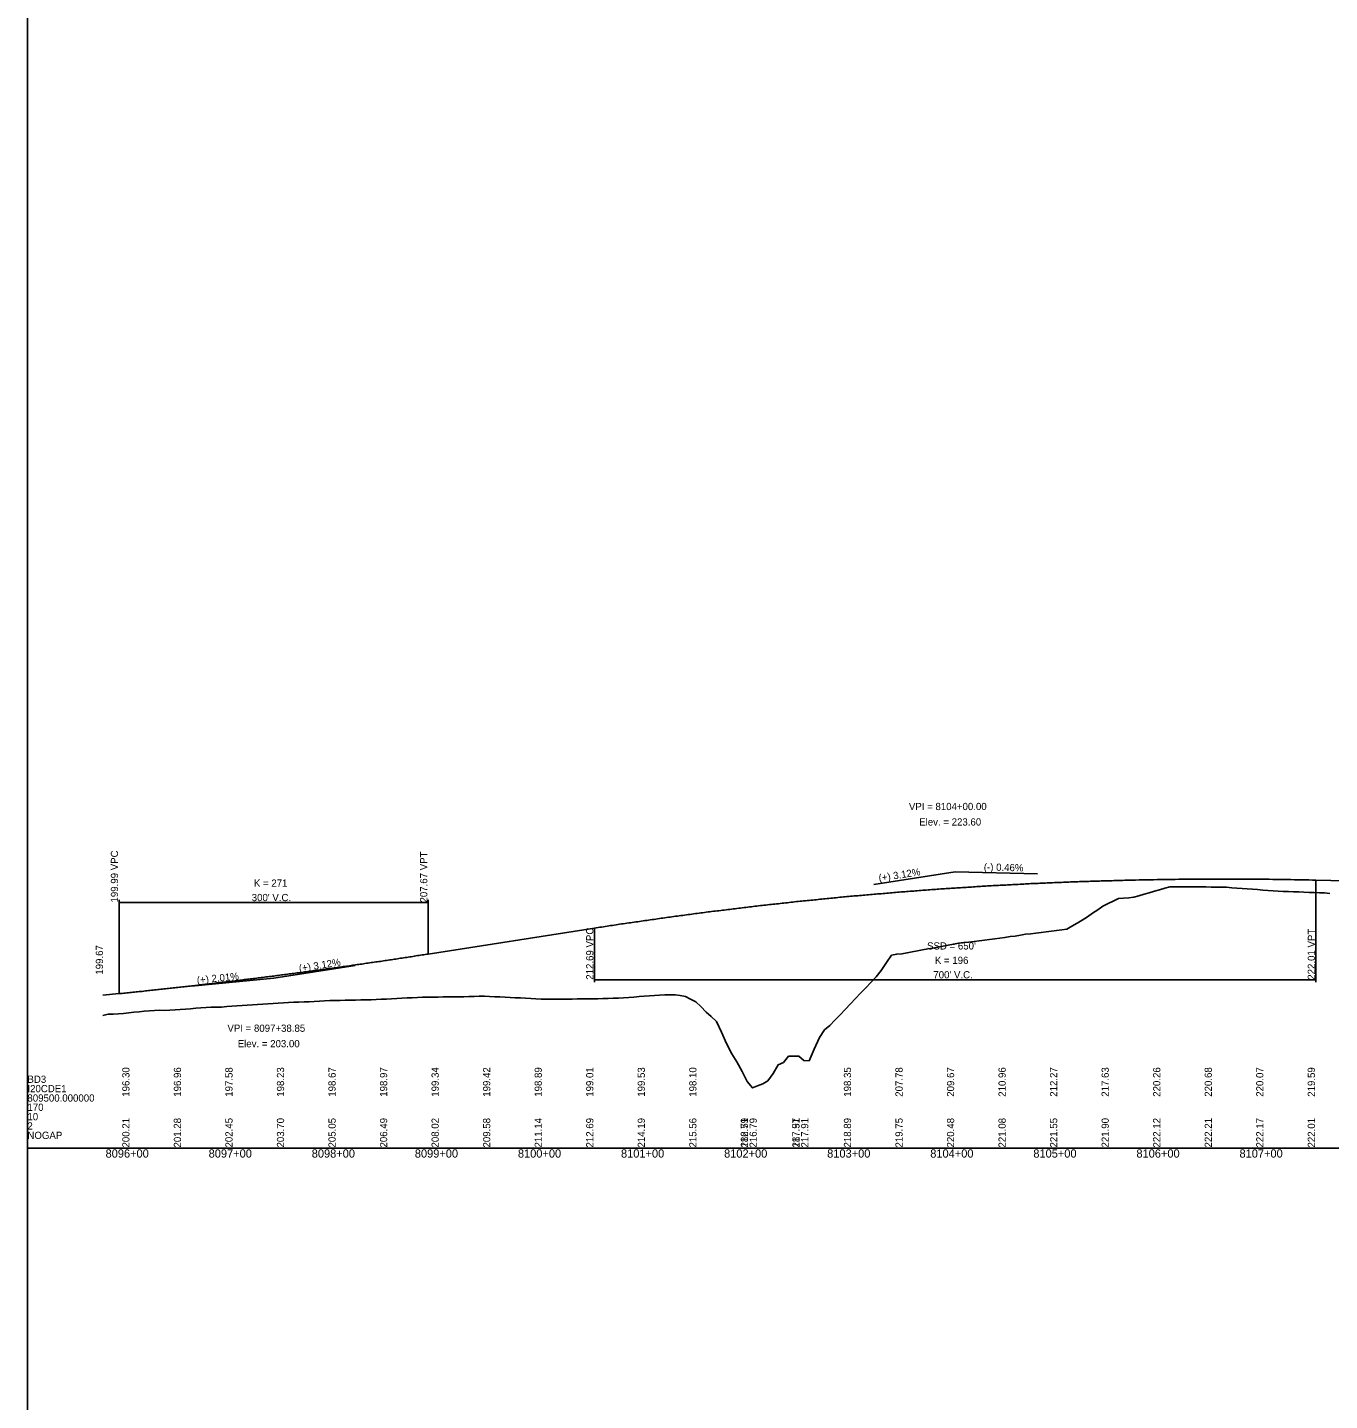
# Model space of a CAD drawing. Extents: x 1838386 to 1955906, y 719739 to 834437.
# Drawn here: x 1895682 to 1896945, y 773245 to 774576 of the extents above; entities that cross this region are included whole.
import ezdxf

# ---------------------------------------------------------------- set-up
doc = ezdxf.new("R2010")
doc.units = 0
for name, color, linetype in [('RD_DDB_GradeTX', 7, 'Continuous'), ('RD_DDB_Profile_EX', 7, 'Continuous'), ('RD_DDB_Profile_Lbl', 7, 'Continuous'), ('RD_DDB_Profile_PR', 7, 'Continuous'), ('RD_DDB_StaTX', 7, 'Continuous'), ('RD_DDB_StripGrade', 7, 'Continuous'), ('RD_DDB_VCLbl', 7, 'Continuous'), ('RD_GPK_Profile_Cell', 7, 'Continuous')]:
    doc.layers.add(name, color=color, linetype=linetype)

msp = doc.modelspace()

# ---------------------------------------------------------------- linework, layer by layer
at = {"layer": 'RD_DDB_GradeTX'}
for p, q in [((1896502.6, 773744.8), (1896581.6, 773757.1)), ((1896661.6, 773755.3), (1896581.6, 773757.1)), ((1895999.5, 773666.5), (1895920.5, 773654.1)), ((1895840.9, 773646.2), (1895920.5, 773654.1))]:
    msp.add_line(p, q, dxfattribs=at)
at = {"layer": 'RD_DDB_Profile_EX'}
for points in [[(1896754.9, 773732.6), (1896759.9, 773734), (1896764.9, 773735.5), (1896769.9, 773736.9), (1896774.9, 773738.4), (1896779.9, 773739.9), (1896784.9, 773741.4), (1896789.9, 773742.6), (1896794.9, 773742.6), (1896799.9, 773742.6), (1896804.9, 773742.6), (1896809.9, 773742.6), (1896814.9, 773742.6), (1896819.9, 773742.6), (1896824.9, 773742.6), (1896829.9, 773742.5), (1896834.9, 773742.5), (1896839.9, 773742.5), (1896844.9, 773742.2), (1896849.9, 773741.8), (1896854.9, 773741.5), (1896859.9, 773741.1), (1896864.9, 773740.7), (1896869.9, 773740.3), (1896874.9, 773740), (1896879.9, 773739.6), (1896884.9, 773739.2), (1896889.9, 773738.9), (1896894.9, 773738.5), (1896899.9, 773738.3), (1896904.9, 773738.1), (1896909.9, 773737.9), (1896914.9, 773737.7), (1896919.9, 773737.5), (1896924.9, 773737.3), (1896929.9, 773737.1), (1896934.9, 773737), (1896939.9, 773736.8), (1896944.9, 773736.3)], [(1896254.9, 773634.8), (1896259.9, 773635), (1896264.9, 773635.4), (1896269.9, 773635.8), (1896274.9, 773636.3), (1896279.9, 773636.7), (1896284.9, 773637), (1896289.9, 773637.2), (1896294.9, 773637.5), (1896299.9, 773637.8), (1896304.9, 773638.1), (1896309.9, 773638.1), (1896314.9, 773637.3), (1896319.9, 773636.3), (1896324.9, 773633.7), (1896329.9, 773631.3), (1896334.9, 773626.6), (1896339.9, 773621), (1896344.9, 773617), (1896349.9, 773612.1), (1896354.9, 773601.9), (1896359.9, 773590.9), (1896364.9, 773580.6), (1896369.9, 773573.1), (1896374.9, 773563.5), (1896379.9, 773553.9), (1896384.9, 773547.7), (1896389.9, 773549.7), (1896394.9, 773551.6), (1896399.9, 773554.6), (1896404.9, 773561.5), (1896409.9, 773570.2), (1896414.9, 773572.3), (1896419.9, 773578.6), (1896424.9, 773578.5), (1896429.9, 773578.4), (1896434.9, 773574.4), (1896439.9, 773573.8), (1896444.9, 773585.2), (1896449.9, 773596.6), (1896454.9, 773603.9), (1896459.9, 773608.2), (1896464.9, 773613.4), (1896469.9, 773618.6), (1896474.9, 773623.8), (1896479.9, 773629.1), (1896484.9, 773634.3), (1896489.9, 773639.5), (1896494.9, 773644.8), (1896499.9, 773650), (1896504.9, 773655.3), (1896509.9, 773661.6), (1896514.9, 773669.2), (1896519.9, 773676.3), (1896524.9, 773677.4), (1896529.9, 773677.7), (1896534.9, 773678.7), (1896539.9, 773679.6), (1896544.9, 773680.5), (1896549.9, 773681.5), (1896554.9, 773682.4), (1896559.9, 773683.3), (1896564.9, 773684.3), (1896569.9, 773685.2), (1896574.9, 773686.2), (1896579.9, 773687.2), (1896584.9, 773688.1), (1896589.9, 773688.6), (1896594.9, 773689.1), (1896599.9, 773689.7), (1896604.9, 773690.4), (1896609.9, 773691), (1896614.9, 773691.7), (1896619.9, 773692.4), (1896624.9, 773693), (1896629.9, 773693.7), (1896634.9, 773694.4), (1896639.9, 773695), (1896644.9, 773695.7), (1896649.9, 773696.8), (1896654.9, 773697.2), (1896659.9, 773697.8), (1896664.9, 773698.4), (1896669.9, 773699), (1896674.9, 773699.6), (1896679.9, 773700.3), (1896684.9, 773700.9), (1896689.9, 773701.7), (1896694.9, 773704.6), (1896699.9, 773707.5), (1896704.9, 773710.4), (1896709.9, 773713.7), (1896714.9, 773717), (1896719.9, 773720.4), (1896724.9, 773723.8), (1896729.9, 773726.4), (1896734.9, 773728.9), (1896739.9, 773731.4), (1896744.9, 773731.6), (1896749.9, 773732.1), (1896754.9, 773732.6)], [(1895754.9, 773617.9), (1895759.9, 773619.1), (1895764.9, 773619.1), (1895769.9, 773619.4), (1895774.9, 773619.9), (1895779.9, 773620.5), (1895784.9, 773621), (1895789.9, 773621.5), (1895794.9, 773622), (1895799.9, 773622.5), (1895804.9, 773622.9), (1895809.9, 773623), (1895814.9, 773622.6), (1895819.9, 773623), (1895824.9, 773623.4), (1895829.9, 773623.8), (1895834.9, 773624.2), (1895839.9, 773624.5), (1895844.9, 773624.9), (1895849.9, 773625.3), (1895854.9, 773625.6), (1895859.9, 773625.9), (1895864.9, 773625.9), (1895869.9, 773626.1), (1895874.9, 773626.5), (1895879.9, 773626.9), (1895884.9, 773627.3), (1895889.9, 773627.6), (1895894.9, 773628), (1895899.9, 773628.4), (1895904.9, 773628.7), (1895909.9, 773629), (1895914.9, 773629.3), (1895919.9, 773629.6), (1895924.9, 773629.9), (1895929.9, 773630.2), (1895934.9, 773630.4), (1895939.9, 773630.7), (1895944.9, 773630.9), (1895949.9, 773631.1), (1895954.9, 773631.3), (1895959.9, 773631.5), (1895964.9, 773631.9), (1895969.9, 773632.1), (1895974.9, 773632.3), (1895979.9, 773632.4), (1895984.9, 773632.6), (1895989.9, 773632.7), (1895994.9, 773632.8), (1895999.9, 773632.9), (1896004.9, 773633), (1896009.9, 773633.1), (1896014.9, 773633.2), (1896019.9, 773633.3), (1896024.9, 773633.6), (1896029.9, 773633.9), (1896034.9, 773634.2), (1896039.9, 773634.4), (1896044.9, 773634.7), (1896049.9, 773634.9), (1896054.9, 773635.2), (1896059.9, 773635.4), (1896064.9, 773635.6), (1896069.9, 773635.7), (1896074.9, 773635.7), (1896079.9, 773635.8), (1896084.9, 773635.9), (1896089.9, 773635.9), (1896094.9, 773636), (1896099.9, 773636), (1896104.9, 773636), (1896109.9, 773636.2), (1896114.9, 773636.4), (1896119.9, 773636.7), (1896124.9, 773636.5), (1896129.9, 773636.3), (1896134.9, 773636.1), (1896139.9, 773635.9), (1896144.9, 773635.6), (1896149.9, 773635.4), (1896154.9, 773635.2), (1896159.9, 773634.9), (1896164.9, 773634.7), (1896169.9, 773634.4), (1896174.9, 773634), (1896179.9, 773633.6), (1896184.9, 773633.6), (1896189.9, 773633.7), (1896194.9, 773633.7), (1896199.9, 773633.8), (1896204.9, 773633.8), (1896209.9, 773633.9), (1896214.9, 773634), (1896219.9, 773634.1), (1896224.9, 773634.1), (1896229.9, 773634.2), (1896234.9, 773634.2), (1896239.9, 773634.4), (1896244.9, 773634.5), (1896249.9, 773634.6), (1896254.9, 773634.8)]]:
    msp.add_lwpolyline(points, dxfattribs=at)
at = {"layer": 'RD_DDB_Profile_PR'}
for p, q in [((1896931.6, 773749.2), (1897881.6, 773727.6)), ((1896070.5, 773677.5), (1896231.6, 773702.6)), ((1895754.9, 773637.5), (1895770.5, 773639.1))]:
    msp.add_line(p, q, dxfattribs=at)
for points in [[(1896231.6, 773702.6), (1896245.6, 773704.8), (1896259.6, 773706.9), (1896273.6, 773708.9), (1896287.6, 773710.9), (1896301.6, 773712.9), (1896315.6, 773714.8), (1896329.6, 773716.7), (1896343.6, 773718.5), (1896357.6, 773720.2), (1896371.6, 773721.9), (1896385.6, 773723.6), (1896399.6, 773725.2), (1896413.6, 773726.7), (1896427.6, 773728.3), (1896441.6, 773729.7), (1896455.6, 773731.1), (1896469.6, 773732.5), (1896483.6, 773733.8), (1896497.6, 773735), (1896511.6, 773736.2), (1896525.6, 773737.4), (1896539.6, 773738.5), (1896553.6, 773739.6), (1896567.6, 773740.6), (1896581.6, 773741.5), (1896595.6, 773742.4), (1896609.6, 773743.3), (1896623.6, 773744.1), (1896637.6, 773744.8), (1896651.6, 773745.6), (1896665.6, 773746.2), (1896679.6, 773746.8), (1896693.6, 773747.4), (1896707.6, 773747.9), (1896721.6, 773748.3), (1896735.6, 773748.7), (1896749.6, 773749.1), (1896763.6, 773749.4), (1896777.6, 773749.7), (1896791.6, 773749.9), (1896805.6, 773750), (1896819.6, 773750.1), (1896833.6, 773750.2), (1896847.6, 773750.2), (1896861.6, 773750.1), (1896875.6, 773750.1), (1896889.6, 773749.9), (1896903.6, 773749.7), (1896917.6, 773749.5), (1896931.6, 773749.2)], [(1895770.5, 773639.1), (1895776.5, 773639.7), (1895782.5, 773640.3), (1895788.5, 773640.9), (1895794.5, 773641.5), (1895800.5, 773642.2), (1895806.5, 773642.8), (1895812.5, 773643.5), (1895818.5, 773644.1), (1895824.5, 773644.8), (1895830.5, 773645.4), (1895836.5, 773646.1), (1895842.5, 773646.8), (1895848.5, 773647.5), (1895854.5, 773648.2), (1895860.5, 773648.9), (1895866.5, 773649.6), (1895872.5, 773650.3), (1895878.5, 773651), (1895884.5, 773651.7), (1895890.5, 773652.5), (1895896.5, 773653.2), (1895902.5, 773653.9), (1895908.5, 773654.7), (1895914.5, 773655.5), (1895920.5, 773656.2), (1895926.5, 773657), (1895932.5, 773657.8), (1895938.5, 773658.6), (1895944.5, 773659.3), (1895950.5, 773660.1), (1895956.5, 773661), (1895962.5, 773661.8), (1895968.5, 773662.6), (1895974.5, 773663.4), (1895980.5, 773664.2), (1895986.5, 773665.1), (1895992.5, 773665.9), (1895998.5, 773666.8), (1896004.5, 773667.6), (1896010.5, 773668.5), (1896016.5, 773669.4), (1896022.5, 773670.2), (1896028.5, 773671.1), (1896034.5, 773672), (1896040.5, 773672.9), (1896046.5, 773673.8), (1896052.5, 773674.7), (1896058.5, 773675.7), (1896064.5, 773676.6), (1896070.5, 773677.5)]]:
    msp.add_spline(points, degree=3, dxfattribs=at)
at = {"layer": 'RD_DDB_VCLbl'}
for p, q in [((1896931.6, 773650.1), (1896931.6, 773749.2)), ((1895770.5, 773730), (1895770.5, 773639.1)), ((1895770.5, 773727.5), (1896070.5, 773727.5)), ((1896070.5, 773730), (1896070.5, 773677.5)), ((1896231.6, 773650.1), (1896231.6, 773702.6)), ((1896231.6, 773652.6), (1896931.6, 773652.6))]:
    msp.add_line(p, q, dxfattribs=at)
at = {"layer": 'RD_GPK_Profile_Cell'}
for q in [(1895681.6, 774739.1), (1900481.6, 773489.1), (1895681.6, 772239.1)]:
    msp.add_line((1895681.6, 773489.1), q, dxfattribs=at)

# ---------------------------------------------------------------- texts
at = {"layer": 'RD_DDB_GradeTX'}
for s, rotation, p in [('(+) 3.12%', 8.8549, (1896507.9, 773747.7)), ('(-) 0.46%', 358.6963, (1896609.3, 773758.5)), ('(+) 3.12%', 8.8549, (1895945.5, 773660.1)), ('(+) 2.01%', 5.7342, (1895846.3, 773648.7))]:
    msp.add_text(s, height=7, rotation=rotation, dxfattribs=at).set_placement(p)
at = {"layer": 'RD_DDB_Profile_Lbl'}
for s, p in [('VPI = 8104+00.00', (1896536.7, 773817.1)), ('Elev. = 223.60', (1896546.7, 773802.1)), ('VPI = 8097+38.85', (1895875.6, 773602.1)), ('Elev. = 203.00', (1895885.6, 773587.1))]:
    msp.add_text(s, height=7, dxfattribs=at).set_placement(p)
msp.add_text('199.67', height=7, rotation=90, dxfattribs=at).set_placement((1895754.9, 773657.5))
at = {"layer": 'RD_DDB_StaTX'}
for s, p in [('8096+00', (1895757.4, 773480.1)), ('8097+00', (1895857.4, 773480.1)), ('8098+00', (1895957.4, 773480.1)), ('8099+00', (1896057.4, 773480.1)), ('8100+00', (1896157.4, 773480.1)), ('8101+00', (1896257.4, 773480.1)), ('8102+00', (1896357.4, 773480.1)), ('8103+00', (1896457.4, 773480.1)), ('8104+00', (1896557.4, 773480.1)), ('8105+00', (1896657.4, 773480.1)), ('8106+00', (1896757.4, 773480.1)), ('8107+00', (1896857.4, 773480.1))]:
    msp.add_text(s, height=8, dxfattribs=at).set_placement(p)
at = {"layer": 'RD_DDB_StripGrade'}
for s, p in [('199.99 VPC', (1895769.5, 773727.5)), ('207.67 VPT', (1896069.5, 773727.5)), ('212.69 VPC', (1896230.6, 773652.6)), ('222.01 VPT', (1896930.6, 773652.6)), ('196.30', (1895780.6, 773539.1)), ('196.96', (1895830.6, 773539.1)), ('197.58', (1895880.6, 773539.1)), ('198.23', (1895930.6, 773539.1)), ('198.67', (1895980.6, 773539.1)), ('198.97', (1896030.6, 773539.1)), ('199.34', (1896080.6, 773539.1)), ('199.42', (1896130.6, 773539.1)), ('198.89', (1896180.6, 773539.1)), ('199.01', (1896230.6, 773539.1)), ('199.53', (1896280.6, 773539.1)), ('198.10', (1896330.6, 773539.1)), ('198.35', (1896480.6, 773539.1)), ('207.78', (1896530.6, 773539.1)), ('209.67', (1896580.6, 773539.1)), ('210.96', (1896630.6, 773539.1)), ('212.27', (1896680.6, 773539.1)), ('217.63', (1896730.6, 773539.1)), ('220.26', (1896780.6, 773539.1)), ('220.68', (1896830.6, 773539.1)), ('220.07', (1896880.6, 773539.1)), ('219.59', (1896930.6, 773539.1)), ('200.21', (1895780.6, 773489.9)), ('201.28', (1895830.6, 773489.9)), ('202.45', (1895880.6, 773489.9)), ('203.70', (1895930.6, 773489.9)), ('205.05', (1895980.6, 773489.9)), ('206.49', (1896030.6, 773489.9)), ('208.02', (1896080.6, 773489.9)), ('209.58', (1896130.6, 773489.9)), ('211.14', (1896180.6, 773489.9)), ('212.69', (1896230.6, 773489.9)), ('214.19', (1896280.6, 773489.9)), ('215.56', (1896330.6, 773489.9)), ('182.51', (1896380.6, 773489.9)), ('216.79', (1896380.6, 773489.9)), ('216.79', (1896389.1, 773489.9)), ('187.57', (1896430.6, 773489.9)), ('217.91', (1896430.6, 773489.9)), ('217.91', (1896439.1, 773489.9)), ('218.89', (1896480.6, 773489.9)), ('219.75', (1896530.6, 773489.9)), ('220.48', (1896580.6, 773489.9)), ('221.08', (1896630.6, 773489.9)), ('221.55', (1896680.6, 773489.9)), ('221.90', (1896730.6, 773489.9)), ('222.12', (1896780.6, 773489.9)), ('222.21', (1896830.6, 773489.9)), ('222.17', (1896880.6, 773489.9)), ('222.01', (1896930.6, 773489.9))]:
    msp.add_text(s, height=7, rotation=90, dxfattribs=at).set_placement(p)
at = {"layer": 'RD_DDB_VCLbl'}
for s, p in [('K = 271', (1895901.3, 773742.8)), ("300' V.C.", (1895899.2, 773728.8)), ("SSD = 650'", (1896554.3, 773681.9)), ('K = 196', (1896561.9, 773667.9)), ("700' V.C.", (1896560.4, 773653.9))]:
    msp.add_text(s, height=7, dxfattribs=at).set_placement(p)
at = {"layer": 'RD_GPK_Profile_Cell'}
for s, p in [('BD3', (1895681.6, 773552.6)), ('I20CDE1', (1895681.6, 773543.5)), ('809500.000000', (1895681.6, 773534.4)), ('170', (1895681.6, 773525.4)), ('10', (1895681.6, 773516.3)), ('2', (1895681.6, 773507.3)), ('NOGAP', (1895681.6, 773498.2))]:
    msp.add_text(s, height=7, dxfattribs=at).set_placement(p)

doc.saveas('drawing.dxf')
